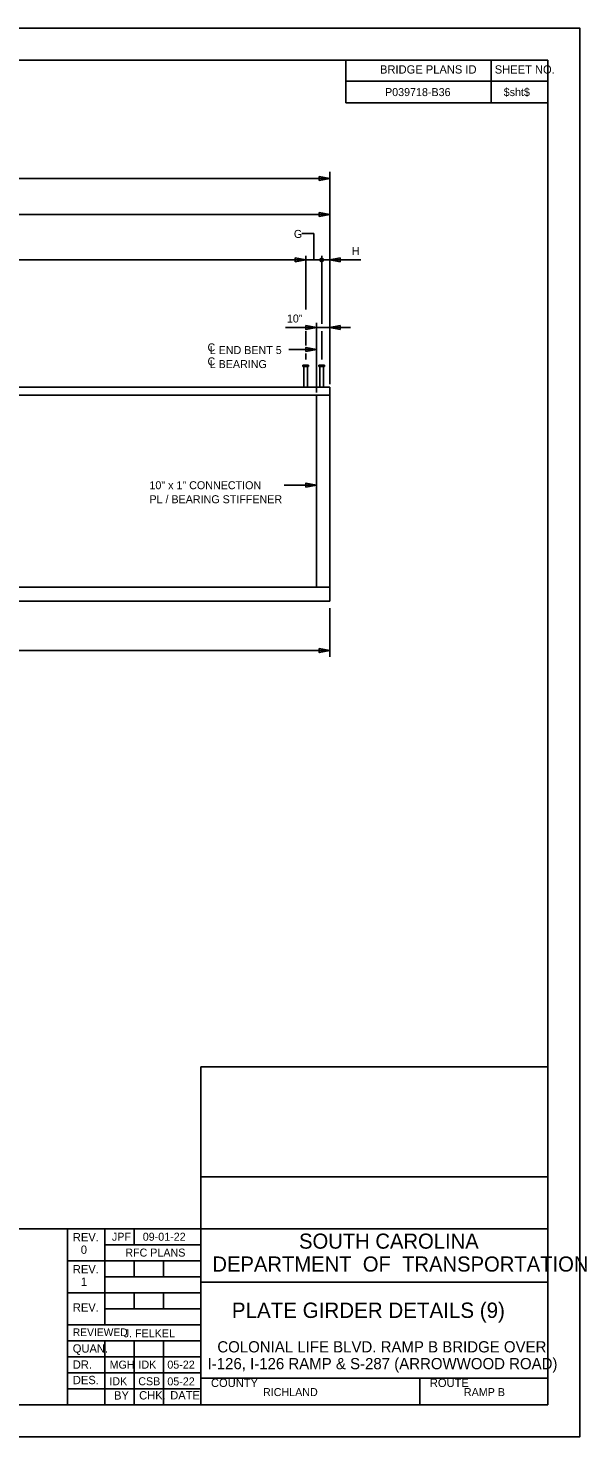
# Model space of a CAD drawing. Extents: x -305 to -161, y -187 to -99.
# Drawn here: x -195.6 to -160.8, y -187.5 to -99.5 of the extents above; entities that cross this region are included whole.
import ezdxf

# ---------------------------------------------------------------- set-up
doc = ezdxf.new("R2010")
doc.units = 0
for name, color, linetype in [('BR_AUTO DIMENSION', 7, 'Continuous'), ('BR_BORDER LINES', 7, 'Continuous'), ('BR_CENTER LINES', 7, 'Continuous'), ('BR_STRUCTURAL STEEL', 7, 'Continuous'), ('BR_TEXT', 7, 'Continuous'), ('Default', 7, 'Continuous'), ('Level 31', 7, 'Continuous')]:
    doc.layers.add(name, color=color, linetype=linetype)

msp = doc.modelspace()

# ---------------------------------------------------------------- linework, layer by layer
at = {"layer": 'BR_AUTO DIMENSION'}
for p, q in [((-284.888, -108.876), (-176.804, -108.876)), ((-176.804, -121.718), (-176.804, -108.463)), ((-284.888, -111.134), (-176.804, -111.134)), ((-178.304, -113.971), (-283.388, -113.971)), ((-178.304, -117.054), (-178.304, -113.71)), ((-174.851, -113.971), (-178.304, -113.971)), ((-177.304, -117.968), (-177.304, -113.71)), ((-179.569, -118.196), (-175.498, -118.196)), ((-178.304, -119.304), (-178.304, -118.423)), ((-177.304, -120.185), (-177.304, -118.423)), ((-177.638, -119.558), (-179.361, -119.558)), ((-178.304, -120.185), (-178.304, -119.822)), ((-177.638, -128.037), (-179.655, -128.037)), ((-176.804, -135.715), (-176.804, -138.768)), ((-284.888, -138.367), (-176.804, -138.367))]:
    msp.add_line(p, q, dxfattribs=at)
for points in [[(-177.454, -108.751), (-176.804, -108.876), (-177.454, -109.001)], [(-177.454, -111.259), (-176.804, -111.134), (-177.454, -111.009)], [(-178.954, -114.096), (-178.304, -113.971), (-178.954, -113.846)], [(-176.154, -114.096), (-176.804, -113.971), (-176.154, -113.846)], [(-178.288, -118.071), (-177.638, -118.196), (-178.288, -118.321)], [(-176.154, -118.321), (-176.804, -118.196), (-176.154, -118.071)], [(-178.288, -119.683), (-177.638, -119.558), (-178.288, -119.433)], [(-178.288, -128.162), (-177.638, -128.037), (-178.288, -127.912)], [(-177.454, -138.242), (-176.804, -138.367), (-177.454, -138.492)]]:
    msp.add_lwpolyline(points, close=True, dxfattribs=at)
msp.add_lwpolyline([(-177.804, -113.971), (-177.804, -112.325), (-178.544, -112.325)], dxfattribs=at)
msp.add_circle((-177.304, -113.971), 0.111, dxfattribs=at)
at = {"layer": 'BR_BORDER LINES'}
for p, q in [((-163.178, -101.489), (-297.843, -101.489)), ((-175.788, -104.156), (-175.788, -101.489)), ((-166.722, -104.156), (-166.722, -101.489)), ((-163.178, -185.489), (-163.178, -101.489)), ((-175.788, -102.808), (-163.178, -102.808)), ((-166.722, -102.808), (-163.178, -102.808)), ((-163.178, -104.156), (-175.788, -104.156)), ((-184.846, -185.489), (-184.846, -164.383)), ((-184.846, -164.383), (-163.178, -164.383)), ((-184.845, -171.242), (-163.178, -171.242)), ((-214.64, -174.489), (-193.18, -174.489)), ((-193.18, -185.489), (-193.18, -174.489)), ((-193.18, -174.489), (-163.178, -174.489)), ((-190.846, -174.489), (-190.846, -180.489)), ((-189.013, -175.489), (-189.013, -174.489)), ((-190.846, -175.489), (-184.846, -175.489)), ((-193.18, -176.489), (-184.846, -176.489)), ((-189.013, -177.489), (-189.013, -176.489)), ((-187.179, -177.489), (-187.179, -176.489)), ((-190.846, -177.489), (-184.846, -177.489)), ((-193.18, -178.489), (-184.846, -178.489)), ((-189.013, -179.489), (-189.013, -178.489)), ((-187.179, -179.489), (-187.179, -178.489)), ((-184.846, -177.822), (-184.846, -177.822)), ((-184.846, -177.823), (-163.178, -177.823)), ((-190.846, -179.489), (-184.846, -179.489)), ((-193.18, -180.489), (-184.846, -180.489)), ((-193.18, -181.489), (-184.846, -181.489)), ((-190.846, -181.489), (-190.846, -185.489)), ((-189.013, -181.489), (-189.013, -185.489)), ((-187.179, -181.489), (-187.179, -185.489)), ((-193.18, -182.489), (-184.846, -182.489)), ((-193.18, -183.489), (-184.846, -183.489)), ((-184.846, -183.823), (-163.178, -183.823)), ((-184.456, -183.823), (-163.178, -183.823)), ((-171.179, -185.489), (-171.179, -183.823)), ((-193.18, -184.489), (-184.846, -184.489)), ((-297.843, -185.489), (-163.178, -185.489))]:
    msp.add_line(p, q, dxfattribs=at)
at = {"layer": 'BR_CENTER LINES'}
msp.add_line((-177.638, -117.887), (-177.638, -122.256), dxfattribs=at)
at = {"layer": 'BR_STRUCTURAL STEEL'}
for p, q in [((-284.888, -121.912), (-176.804, -121.912)), ((-176.804, -121.912), (-176.804, -122.412)), ((-284.888, -122.412), (-176.804, -122.412)), ((-177.638, -122.412), (-177.638, -134.412)), ((-176.804, -122.412), (-176.804, -134.412)), ((-284.888, -134.412), (-176.804, -134.412)), ((-176.804, -134.412), (-176.804, -135.287)), ((-284.888, -135.287), (-176.804, -135.287))]:
    msp.add_line(p, q, dxfattribs=at)
at = {"layer": 'Default'}
for p, q in [((-178.476, -120.537), (-178.476, -120.631)), ((-178.476, -120.537), (-178.132, -120.537)), ((-178.132, -120.537), (-178.132, -120.631)), ((-177.476, -120.537), (-177.476, -120.631)), ((-177.476, -120.537), (-177.132, -120.537)), ((-177.132, -120.537), (-177.132, -120.631)), ((-178.476, -120.631), (-178.132, -120.631)), ((-178.414, -120.631), (-178.414, -121.912)), ((-178.195, -120.631), (-178.195, -121.912)), ((-177.476, -120.631), (-177.132, -120.631)), ((-177.414, -120.631), (-177.414, -121.912)), ((-177.195, -120.631), (-177.195, -121.912))]:
    msp.add_line(p, q, dxfattribs=at)
at = {"layer": 'Level 31'}
msp.add_line((-174.011, -179.583), (-174.011, -179.583), dxfattribs=at)
msp.add_lwpolyline([(-305.176, -187.489), (-161.176, -187.489), (-161.176, -99.489), (-305.176, -99.489)], close=True, dxfattribs=at)

# ---------------------------------------------------------------- texts
at = {"layer": 'BR_AUTO DIMENSION'}
for s, p in [('G', (-179.04, -112.593)), ('H', (-175.424, -113.652)), ('10"', (-179.476, -117.877))]:
    msp.add_text(s, height=0.5, rotation=360, dxfattribs=at).set_placement(p)
at = {"layer": 'BR_TEXT'}
for s, height, p in [('BRIDGE PLANS ID', 0.52, (-173.663, -102.327)), ('SHEET NO.', 0.52, (-166.499, -102.327)), ('P039718-B36', 0.5, (-173.348, -103.732)), ('$sht$', 0.5, (-165.939, -103.732)), ('REV.', 0.52, (-192.841, -175.277)), ('JPF', 0.5, (-190.4, -175.239)), ('09-01-22', 0.5, (-188.475, -175.239)), ('SOUTH CAROLINA', 0.94348, (-178.718, -175.735)), ('0', 0.52, (-192.345, -176.057)), ('RFC PLANS', 0.5, (-189.566, -176.229)), ('REV.', 0.52, (-192.841, -177.277)), ('DEPARTMENT  OF  TRANSPORTATION', 0.94348, (-184.129, -177.166)), ('1', 0.52, (-192.337, -178.057)), ('REV.', 0.52, (-192.841, -179.667)), ('PLATE GIRDER DETAILS (9)', 0.96, (-182.913, -180.063)), ('REVIEWED', 0.48, (-192.843, -181.195)), ('J. FELKEL', 0.5, (-189.664, -181.272)), ('QUAN.', 0.52, (-192.846, -182.229)), ('COLONIAL LIFE BLVD. RAMP B BRIDGE OVER', 0.7, (-183.82, -182.216)), ('DR.', 0.52, (-192.845, -183.235)), ('MGH', 0.5, (-190.544, -183.228)), ('IDK', 0.5, (-188.747, -183.228)), ('05-22', 0.5, (-186.94, -183.228)), ('I-126, I-126 RAMP & S-287 (ARROWWOOD ROAD) ', 0.7, (-184.429, -183.266)), ('DES.', 0.52, (-192.841, -184.2)), ('IDK', 0.5, (-190.562, -184.267)), ('CSB', 0.5, (-188.756, -184.267)), ('05-22', 0.5, (-186.94, -184.276)), ('COUNTY', 0.52, (-184.217, -184.376)), ('ROUTE', 0.52, (-170.55, -184.376)), ('BY', 0.52, (-190.265, -185.161)), ('CHK.', 0.52, (-188.701, -185.156)), ('DATE', 0.52, (-186.761, -185.156)), ('RICHLAND', 0.5, (-180.968, -184.944)), ('RAMP B', 0.5, (-168.424, -184.944))]:
    msp.add_text(s, height=height, dxfattribs=at).set_placement(p)
for s, p in [('C', (-184.431, -119.681)), ('L END BENT 5', (-184.296, -119.848)), ('C', (-184.431, -120.556)), ('L BEARING', (-184.296, -120.723)), ('10" x 1" CONNECTION ', (-188.059, -128.293)), ('PL / BEARING STIFFENER', (-188.059, -129.168))]:
    msp.add_text(s, height=0.5, rotation=360, dxfattribs=at).set_placement(p)

doc.saveas('drawing.dxf')
